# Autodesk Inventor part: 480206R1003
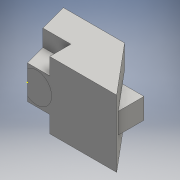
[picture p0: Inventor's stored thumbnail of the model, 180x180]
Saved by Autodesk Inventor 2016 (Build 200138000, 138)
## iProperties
Created: 2018-02
Part Number: 480206R1003
Material: 일반
Document SubType Name: Modeling
Designer: USER
Density: 1 g/cm^3
Appearance: 기본값
Author: USER
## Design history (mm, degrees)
sketch "스케치1"
  geometry: L1 (0, 0)-(80, 0); L2 (80, 0)-(43.08, 44); L3 (43.08, 44)-(-11.79, 44); L4 (-11.79, 44)-(0, 0)
  constraints: 8 end point, 1 horizontal, 1 parallel
  dimensions: "d0" = 80 distance of L1.start L1.end; "d1" = 50 deg angle of L1 L2; "d2" = 105 deg angle of L4 L3; "d4" = 44 distance between parallel lines of L1 L3
extrude "돌출1" new body sketch "스케치1" stored distance "d5" = 60; taper "d6" = 0 deg
sketch "스케치2"
  geometry: L1 (-11.79, 44)-(0, 0) reference; L2 (0, 0)-(80, 0) reference
sketch "스케치3"
  geometry: L1 (-11.79, 44)-(43.08, 44) reference; L2 (25.58, 44)-(28.795, 32); L3 (28.795, 32)-(53.149, 32); L4 (43.08, 44)-(80, 0) reference; 1 further point
  constraints: 4 end point, 2 point on line, 1 horizontal
  dimensions: "d9" = 75 deg angle of L3 L2; "d10" = 12 distance between parallel lines of L3 L1; "d11" = 17.5 distance of L2.start L1.end
extrude "돌출2" cut sketch "스케치3" stored distance "d12" = 18.5; taper "d13" = 0 deg
sketch "스케치4"
  geometry: L1 (43.08, 44)-(80, 0) reference; L2 (53.149, 32)-(28.795, 32) reference; L3 (53.149, 32)-(72.5, 32); L4 (72.5, 32)-(72.5, 8.938); 1 further point
  constraints: 4 end point, 1 horizontal, 1 perpendicular, 1 point on line
  dimensions: "d14" = 12 vertical distance of L3.end L1.start (derived); "d15" = 7.5 horizontal distance of L1.end L3.end
extrude "돌출3" join sketch "스케치4" stored distance "d16" = 18.5; taper "d17" = 0 deg
sketch "스케치5"
  geometry: 1 further point
sketch "스케치6"
  geometry: 1 further point
sketch "스케치7"
  geometry: L1 (-11.79, 44)-(0, 0) reference; L2 (-5.091, 19)-(20, 19); L3 (20, 19)-(20, 0); L4 (0, 0)-(80, 0) reference
  constraints: 4 end point, 2 point on line, 1 horizontal, 1 perpendicular
  dimensions: "d18" = 60 distance of L4.end L3.end; "d19" = 80 distance of L1.end L4.end (derived); "d20" = 19 distance between parallel lines of L4 L2
extrude "돌출4" cut sketch "스케치7" distance "d21" = 15; taper "d22" = 0 deg
sketch "스케치8"
  geometry: L1 (0, 0)-(54.869, 0) reference; L2 (0, 0)-(0, -60) reference; C1 r 5.5 at (20, -30); 1 further point
  constraints: 1 centre point
  dimensions: "d23" = 20 horizontal distance of C1.centre L1.start; "d24" = 11 diameter of C1; "d25" = 30 distance from line of C1.centre L1
extrude "돌출5" cut sketch "스케치8" distance "d26" = 30.5; taper "d27" = 0 deg
sketch "스케치9"
  geometry: L1 (60.462, 9.25)-(64.29, 9.25) reference; L2 (64.29, 9.25)-(64.29, -9.25) reference; L3 (64.29, -9.25)-(60.462, -9.25) reference; L4 (60.462, -9.25)-(60.462, -30) reference; L5 (60.462, -30)-(11.79, -30) reference; L6 (11.79, -30)-(11.79, -15) reference; L7 (11.79, -15)-(-11.828, -15) reference; L8 (-11.828, -15)-(-11.828, 15) reference; L9 (-11.828, 15)-(11.79, 15) reference; L10 (11.79, 15)-(11.79, 30) reference; L11 (11.79, 30)-(60.462, 30) reference; L12 (60.462, 30)-(60.462, 9.25) reference; L13 (-8.21, -15)-(-8.21, 15) reference; L14 (-8.21, 10.716)-(-8.21, -10.716); C1 r 5.5 at (0, 0) reference; A1 r 13.5 centre (0, 0) between (-8.21, -10.716) and (-8.21, 10.716); 1 further point
  constraints: 2 end point, 2 point on circle, 2 point on line, 1 centre point, 1 coincident, 1 collinear
  dimensions: "d28" = 27 diameter of A1
extrude "돌출6" new body sketch "스케치9" distance "d29" = 13.5; taper "d30" = 0 deg
sketch "스케치10"
  geometry: 1 further point
node "솔리드1"
mirror "대칭1"
node "솔리드2"
node "절단 모서리 투영1"
